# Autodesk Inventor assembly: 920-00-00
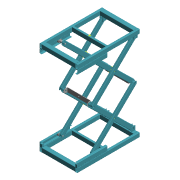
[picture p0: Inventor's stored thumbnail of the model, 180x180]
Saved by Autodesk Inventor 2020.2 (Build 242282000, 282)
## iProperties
Created: 2015-10
Part Number: 920-00-00
Document SubType Name: Assembly
Designer: F.Stasiak
Catalog Web Link: www.expertbooks.pl
Manager: www.cadconsulting.pl
Company: Fabian Stasiak CAD Consulting
Author: F.Stasiak
Subject: Zbiór ćwiczeń. Autodesk Inventor 2020. Kurs Professional
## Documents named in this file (8)
- C:\2020_Kurs_Professional\R3 Dynamika\920-00-00.iam
- C:\2020_Kurs_Professional\R3 Dynamika\Komponenty_dyn\900-01-00.iam
- C:\2020_Kurs_Professional\R3 Dynamika\Komponenty_dyn\900-03-00.iam
- C:\2020_Kurs_Professional\R3 Dynamika\Komponenty_dyn\900-04-00.iam
- C:\2020_Kurs_Professional\R3 Dynamika\Komponenty_dyn\900-02-00.iam
- C:\2020_Kurs_Professional\R3 Dynamika\Komponenty_dyn\900-05-01.ipt
- C:\2020_Kurs_Professional\R3 Dynamika\Komponenty_dyn\900-06-01.ipt
- C:\2020_Kurs_Professional\R3 Dynamika\Komponenty_dyn\900-07-02.ipt
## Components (14 placed, 7 different names)
1. 900-01-00:1 [sub-assembly] — PODNIESIENIE, Wstaw:10, Styczny:3
2. 900-02-00:1 [sub-assembly] — PODNIESIENIE, Wstaw:16, Wstaw:17
3. 900-03-00:1 [sub-assembly] — Wstaw:10, Wstaw:11, Wstaw:12, Wstaw:14, Zestawiający:23, Zestawiający:24
4. 900-03-00:2 [sub-assembly] — Wstaw:8, Wstaw:9, Wstaw:15, Zestawiający:19, Zestawiający:21, Zestawiający:22
5. 900-04-00:2 [sub-assembly] — Wstaw:17, Zestawiający:19
6. 900-04-00:6 [sub-assembly] — Wstaw:7, Wstaw:11
7. 900-04-00:4 [sub-assembly] — Wstaw:14, Wstaw:15, Wstaw:16
8. 900-04-00:5 [sub-assembly] — Wstaw:6, Wstaw:12, Zestawiający:21
9. 900-05-01:1 — Wstaw:6
10. 900-05-01:2 — Wstaw:7, Styczny:3
11. 900-06-01:1 — Wstaw:9
12. 900-06-01:2 — Wstaw:8
13. 900-07-02:1 — Zestawiający:23, Zestawiający:20, Zestawiający:24
14. 900-07-02:2 — Zestawiający:20, Zestawiający:22
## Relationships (19: Insert 11, Mate 7, Tangent 1)
- PODNIESIENIE [Mate]: 900-01-00:1 ↔ 900-02-00:1
- Styczny:3 [Tangent]: 900-01-00:1 ↔ 900-05-01:2
- Wstaw:6 [Insert]: 900-04-00:5 ↔ 900-05-01:1
- Wstaw:7 [Insert]: 900-04-00:6 ↔ 900-05-01:2
- Wstaw:8 [Insert]: 900-03-00:2 ↔ 900-06-01:2
- Wstaw:9 [Insert]: 900-03-00:2 ↔ 900-06-01:1
- Wstaw:10 [Insert]: 900-01-00:1 ↔ 900-03-00:1
- Wstaw:11 [Insert]: 900-03-00:1 ↔ 900-04-00:6
- Wstaw:12 [Insert]: 900-03-00:1 ↔ 900-04-00:5
- Wstaw:14 [Insert]: 900-03-00:1 ↔ 900-04-00:4
- Wstaw:15 [Insert]: 900-03-00:2 ↔ 900-04-00:4
- Wstaw:16 [Insert]: 900-02-00:1 ↔ 900-04-00:4
- Wstaw:17 [Insert]: 900-02-00:1 ↔ 900-04-00:2
- Zestawiający:19 [Mate]: 900-03-00:2 ↔ 900-04-00:2
- Zestawiający:23 [Mate]: 900-03-00:1 ↔ 900-07-02:1
- Zestawiający:21 [Mate]: 900-03-00:2 ↔ 900-04-00:5
- Zestawiający:20 [Mate]: 900-07-02:1 ↔ 900-07-02:2
- Zestawiający:22 [Mate]: 900-03-00:2 ↔ 900-07-02:2
- Zestawiający:24 [Mate]: 900-03-00:1 ↔ 900-07-02:1
